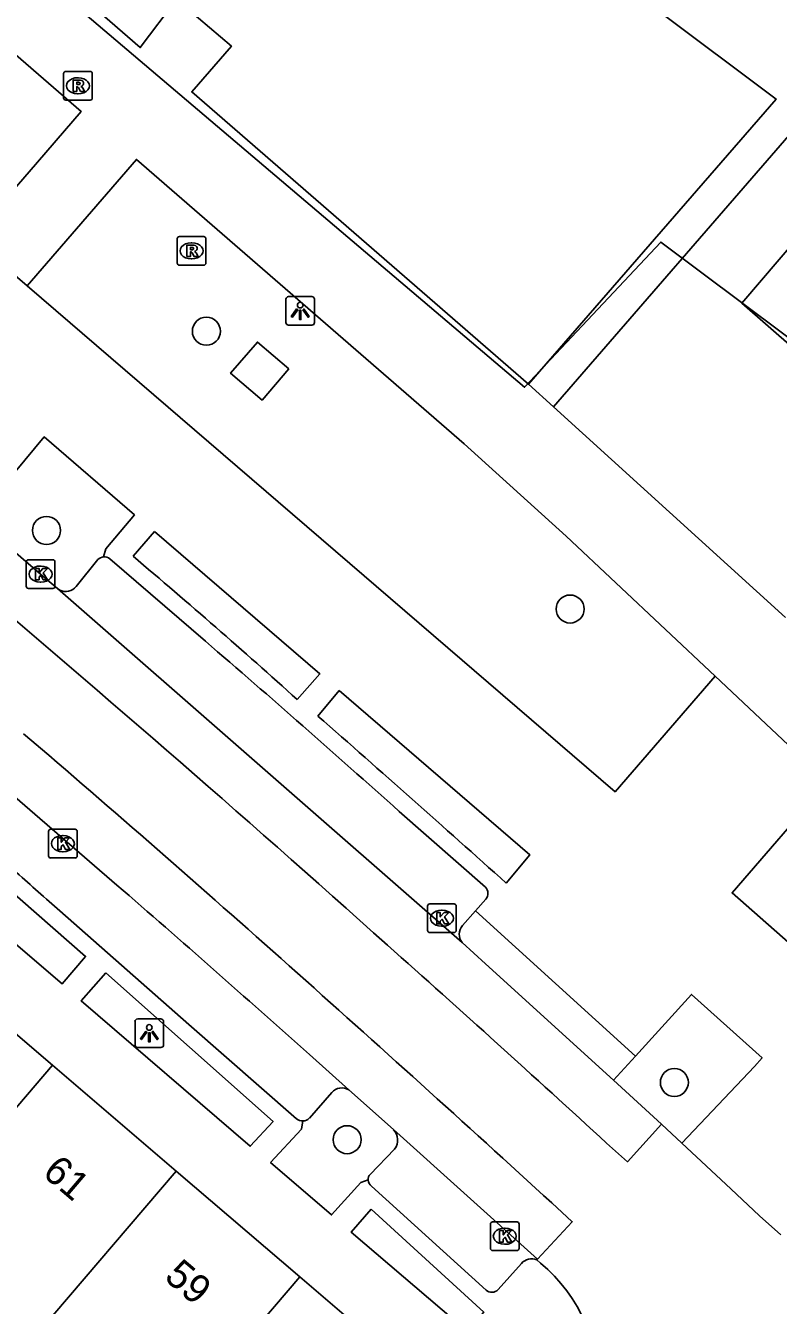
# Model space of a CAD drawing. Extents: x 159718 to 160783, y 383290 to 384030.
# Drawn here: x 160388.25 to 160414.5, y 383658.33 to 383702.97 of the extents above; entities that cross this region are included whole.
import ezdxf

# ---------------------------------------------------------------- set-up
doc = ezdxf.new("R2010")
doc.units = 0
for name, color, linetype in [('IMGEO_Boom', 7, 'Continuous'), ('IMGEO_Groenvoorziening', 7, 'Continuous'), ('IMGEO_Kolk', 7, 'Continuous'), ('IMGEO_Lichtpunt', 7, 'Continuous'), ('IMGEO_Pand', 7, 'Continuous'), ('IMGEO_Pand_nummerreeks', 7, 'Continuous'), ('IMGEO_Pand_overbouw', 7, 'Continuous'), ('IMGEO_Parkeervlak_open', 7, 'Continuous'), ('IMGEO_Rijbaan_lokaal_gesloten', 7, 'Continuous'), ('IMGEO_Rijbaan_lokaal_open', 7, 'Continuous'), ('IMGEO_Rioolput', 7, 'Continuous'), ('IMGEO_Voetpad_open', 7, 'Continuous')]:
    doc.layers.add(name, color=color, linetype=linetype)

msp = doc.modelspace()

# ---------------------------------------------------------------- linework, layer by layer
at = {"layer": 'IMGEO_Boom'}
for centre in [(160394.554, 383692.31), (160388.977, 383685.362), (160407.24, 383682.62), (160410.875, 383666.105), (160399.463, 383664.11)]:
    msp.add_circle(centre, 0.489, dxfattribs=at)
at = {"layer": 'IMGEO_Groenvoorziening'}
msp.add_lwpolyline([(160397.427, 383690.994), (160396.331, 383691.934), (160395.399, 383690.847), (160396.495, 383689.907), (160397.427, 383690.994)], dxfattribs=at)
at = {"layer": 'IMGEO_Kolk'}
for p, q in [((160388.272, 383683.413), (160388.272, 383684.265)), ((160388.347, 383684.339), (160389.199, 383684.339)), ((160389.273, 383684.265), (160389.273, 383683.413)), ((160388.76, 383684.119), (160388.785, 383684.119)), ((160389.199, 383683.339), (160388.347, 383683.339)), ((160388.783, 383683.559), (160388.758, 383683.559)), ((160389.046, 383674.01), (160389.046, 383674.862)), ((160389.121, 383674.936), (160389.973, 383674.936)), ((160390.047, 383674.862), (160390.047, 383674.01)), ((160389.534, 383674.716), (160389.559, 383674.716)), ((160389.973, 383673.936), (160389.121, 383673.936)), ((160389.557, 383674.156), (160389.532, 383674.156)), ((160402.268, 383671.408), (160402.268, 383672.26)), ((160402.343, 383672.334), (160403.195, 383672.334)), ((160402.756, 383672.114), (160402.781, 383672.114)), ((160403.269, 383672.26), (160403.269, 383671.408)), ((160403.195, 383671.334), (160402.343, 383671.334)), ((160402.779, 383671.554), (160402.754, 383671.554)), ((160404.461, 383660.315), (160404.461, 383661.167)), ((160404.536, 383661.241), (160405.388, 383661.241)), ((160404.949, 383661.021), (160404.974, 383661.021)), ((160405.462, 383661.167), (160405.462, 383660.315)), ((160405.388, 383660.241), (160404.536, 383660.241)), ((160404.972, 383660.461), (160404.947, 383660.461))]:
    msp.add_line(p, q, dxfattribs=at)
for points in [[(160388.272, 383683.413), (160388.272, 383684.265)], [(160388.347, 383684.339), (160389.199, 383684.339)], [(160389.273, 383684.265), (160389.273, 383683.413)], [(160388.593, 383684.039), (160388.716, 383684.039), (160388.716, 383683.888), (160388.846, 383684.039), (160389.01, 383684.039), (160388.864, 383683.888), (160389.017, 383683.639), (160388.865, 383683.639), (160388.78, 383683.803), (160388.716, 383683.736), (160388.716, 383683.639), (160388.593, 383683.639), (160388.593, 383684.039)], [(160389.199, 383683.339), (160388.347, 383683.339)], [(160389.046, 383674.01), (160389.046, 383674.862)], [(160389.121, 383674.936), (160389.973, 383674.936)], [(160390.047, 383674.862), (160390.047, 383674.01)], [(160389.367, 383674.636), (160389.49, 383674.636), (160389.49, 383674.485), (160389.62, 383674.636), (160389.784, 383674.636), (160389.638, 383674.485), (160389.791, 383674.236), (160389.639, 383674.236), (160389.554, 383674.4), (160389.49, 383674.333), (160389.49, 383674.236), (160389.367, 383674.236), (160389.367, 383674.636)], [(160389.973, 383673.936), (160389.121, 383673.936)], [(160402.268, 383671.408), (160402.268, 383672.26)], [(160402.343, 383672.334), (160403.195, 383672.334)], [(160403.269, 383672.26), (160403.269, 383671.408)], [(160402.589, 383672.034), (160402.712, 383672.034), (160402.712, 383671.883), (160402.842, 383672.034), (160403.006, 383672.034), (160402.86, 383671.883), (160403.013, 383671.634), (160402.861, 383671.634), (160402.776, 383671.798), (160402.712, 383671.731), (160402.712, 383671.634), (160402.589, 383671.634), (160402.589, 383672.034)], [(160403.195, 383671.334), (160402.343, 383671.334)], [(160404.461, 383660.315), (160404.461, 383661.167)], [(160404.536, 383661.241), (160405.388, 383661.241)], [(160405.462, 383661.167), (160405.462, 383660.315)], [(160404.782, 383660.941), (160404.905, 383660.941), (160404.905, 383660.79), (160405.035, 383660.941), (160405.199, 383660.941), (160405.053, 383660.79), (160405.206, 383660.541), (160405.054, 383660.541), (160404.969, 383660.705), (160404.905, 383660.638), (160404.905, 383660.541), (160404.782, 383660.541), (160404.782, 383660.941)], [(160405.388, 383660.241), (160404.536, 383660.241)]]:
    msp.add_lwpolyline(points, dxfattribs=at)
for centre, start, end in [((160388.349, 383684.263), 91.552, 178.448), ((160388.349, 383684.263), 91.552, 178.448), ((160389.197, 383684.263), 1.552, 88.448), ((160389.197, 383684.263), 1.552, 88.448), ((160388.349, 383683.415), 181.552, 268.448), ((160388.349, 383683.415), 181.552, 268.448), ((160389.197, 383683.415), 271.552, 358.448), ((160389.197, 383683.415), 271.552, 358.448), ((160389.123, 383674.86), 91.552, 178.448), ((160389.123, 383674.86), 91.552, 178.448), ((160389.971, 383674.86), 1.552, 88.448), ((160389.971, 383674.86), 1.552, 88.448), ((160389.123, 383674.012), 181.552, 268.448), ((160389.123, 383674.012), 181.552, 268.448), ((160389.971, 383674.012), 271.552, 358.448), ((160389.971, 383674.012), 271.552, 358.448), ((160402.345, 383672.258), 91.552, 178.448), ((160402.345, 383672.258), 91.552, 178.448), ((160403.193, 383672.258), 1.552, 88.448), ((160403.193, 383672.258), 1.552, 88.448), ((160402.345, 383671.41), 181.552, 268.448), ((160402.345, 383671.41), 181.552, 268.448), ((160403.193, 383671.41), 271.552, 358.448), ((160403.193, 383671.41), 271.552, 358.448), ((160404.538, 383661.165), 91.552, 178.448), ((160404.538, 383661.165), 91.552, 178.448), ((160405.386, 383661.165), 1.552, 88.448), ((160405.386, 383661.165), 1.552, 88.448), ((160404.538, 383660.317), 181.552, 268.448), ((160404.538, 383660.317), 181.552, 268.448), ((160405.386, 383660.317), 271.552, 358.448), ((160405.386, 383660.317), 271.552, 358.448)]:
    msp.add_arc(centre, 0.0765, start, end, dxfattribs=at)
for centre, major_axis, ratio, start_param, end_param in [((160388.759, 383683.839), (-0.387, 0.002), 0.722429, 4.712389, 7.853982), ((160388.784, 383683.839), (-0.39, 0.002), 0.717154, 1.570796, 4.712389), ((160389.533, 383674.436), (-0.387, 0.002), 0.722429, 4.712389, 7.853982), ((160389.558, 383674.436), (-0.39, 0.002), 0.717154, 1.570796, 4.712389), ((160402.755, 383671.834), (-0.387, 0.002), 0.722429, 4.712389, 7.853982), ((160402.78, 383671.834), (-0.39, 0.002), 0.717154, 1.570796, 4.712389), ((160404.948, 383660.741), (-0.387, 0.002), 0.722429, 4.712389, 7.853982), ((160404.973, 383660.741), (-0.39, 0.002), 0.717154, 1.570796, 4.712389)]:
    msp.add_ellipse(centre, major_axis=major_axis, ratio=ratio, start_param=start_param, end_param=end_param, dxfattribs=at)
at = {"layer": 'IMGEO_Lichtpunt'}
for p, q in [((160397.328, 383693.423), (160397.328, 383692.616)), ((160397.328, 383693.423), (160397.328, 383692.616)), ((160398.23, 383693.518), (160397.422, 383693.518)), ((160398.23, 383693.518), (160397.422, 383693.518)), ((160398.324, 383692.616), (160398.324, 383693.423)), ((160398.324, 383692.616), (160398.324, 383693.423)), ((160397.422, 383692.522), (160398.23, 383692.522)), ((160397.422, 383692.522), (160398.23, 383692.522)), ((160392.064, 383668.227), (160392.064, 383667.42)), ((160392.064, 383668.227), (160392.064, 383667.42)), ((160392.966, 383668.322), (160392.158, 383668.322)), ((160392.966, 383668.322), (160392.158, 383668.322)), ((160393.06, 383667.42), (160393.06, 383668.227)), ((160393.06, 383667.42), (160393.06, 383668.227)), ((160392.158, 383667.326), (160392.966, 383667.326)), ((160392.158, 383667.326), (160392.966, 383667.326))]:
    msp.add_line(p, q, dxfattribs=at)
for points in [[(160397.702, 383693.087), (160397.741, 383693.059), (160397.553, 383692.797), (160397.515, 383692.824), (160397.702, 383693.087)], [(160397.804, 383693.039), (160397.851, 383693.039), (160397.851, 383692.717), (160397.804, 383692.717), (160397.804, 383693.039)], [(160397.914, 383693.059), (160397.952, 383693.086), (160398.139, 383692.824), (160398.1, 383692.796), (160397.914, 383693.059)], [(160392.438, 383667.891), (160392.477, 383667.863), (160392.289, 383667.601), (160392.251, 383667.628), (160392.438, 383667.891)], [(160392.54, 383667.843), (160392.587, 383667.843), (160392.587, 383667.521), (160392.54, 383667.521), (160392.54, 383667.843)], [(160392.65, 383667.863), (160392.688, 383667.89), (160392.875, 383667.628), (160392.836, 383667.6), (160392.65, 383667.863)]]:
    msp.add_lwpolyline(points, dxfattribs=at)
for centre in [(160397.827, 383693.221), (160392.563, 383668.025)]:
    msp.add_circle(centre, 0.0994, dxfattribs=at)
for centre, start, end in [((160397.422, 383693.423), 90, 180), ((160397.422, 383693.423), 90, 180), ((160398.23, 383693.423), 0, 90), ((160398.23, 383693.423), 0, 90), ((160397.422, 383692.616), 180, 270), ((160397.422, 383692.616), 180, 270), ((160398.23, 383692.616), 270, 0), ((160398.23, 383692.616), 270, 360), ((160392.158, 383668.227), 90, 180), ((160392.158, 383668.227), 90, 180), ((160392.966, 383668.227), 0, 90), ((160392.966, 383668.227), 0, 90), ((160392.158, 383667.42), 180, 270), ((160392.158, 383667.42), 180, 270), ((160392.966, 383667.42), 270, 0), ((160392.966, 383667.42), 270, 360)]:
    msp.add_arc(centre, 0.0946, start, end, dxfattribs=at)
at = {"layer": 'IMGEO_Pand'}
for points in [[(160401.99, 383715.21), (160399.21, 383711.499), (160401.631, 383709.396), (160401.952, 383709.766), (160414.42, 383700.405), (160405.79, 383690.466)], [(160405.79, 383690.466), (160394.044, 383700.656), (160395.427, 383702.249), (160393.513, 383703.895), (160392.245, 383702.203), (160378.05, 383714.53)], [(160384.875, 383670.399), (160389.186, 383666.706)], [(160389.186, 383666.706), (160380.109, 383656.074), (160379.984, 383655.928)], [(160393.496, 383663.015), (160389.186, 383666.706)], [(160393.496, 383663.015), (160388.65, 383657.338)], [(160397.807, 383659.322), (160393.496, 383663.015)], [(160397.807, 383659.322), (160388.712, 383648.669)], [(160402.121, 383655.627), (160397.807, 383659.322)]]:
    msp.add_lwpolyline(points, dxfattribs=at)
at = {"layer": 'IMGEO_Pand_overbouw'}
msp.add_lwpolyline([(160329.238, 383785.121), (160331.99, 383780.945), (160334.29, 383776.804), (160336.214, 383773.114), (160339.132, 383767.518), (160356.871, 383731.789), (160405.652, 383690.358), (160410.402, 383695.422), (160427.513, 383682.61), (160420.977, 383676.643), (160427.906, 383670.57), (160434.977, 383677.001), (160452.682, 383663.643), (160457.733, 383668.166), (160454.133, 383672.121), (160456.593, 383674.32), (160452.291, 383679.222), (160501.162, 383722.964), (160422.396, 383781.748), (160424.644, 383785.027)], dxfattribs=at)
at = {"layer": 'IMGEO_Parkeervlak_open'}
for points in [[(160390.009, 383683.409), (160390.773, 383684.349)], [(160389.361, 383683.332), (160389.44, 383683.28)], [(160398.144, 383664.855), (160398.931, 383665.755)], [(160400.264, 383662.9), (160401.116, 383663.785)]]:
    msp.add_lwpolyline(points, dxfattribs=at)
for centre, radius, start, end in [((160390.993, 383684.119), 0.318, 94.8322, 133.6974), ((160389.648, 383683.684), 0.454, 242.8196, 322.728), ((160399.279, 383665.463), 0.454, 58.1088, 140.0566), ((160397.913, 383665.102), 0.338, 271.5028, 313.0756), ((160400.707, 383664.103), 0.518, 322.1077, 43.4901), ((160400.472, 383662.714), 0.279, 138.211, 181.3943)]:
    msp.add_arc(centre, radius, start, end, dxfattribs=at)
at = {"layer": 'IMGEO_Rijbaan_lokaal_gesloten'}
for points in [[(160389.361, 383683.332), (160388.773, 383683.839), (160386.776, 383685.54)], [(160403.476, 383670.988), (160389.361, 383683.332)], [(160385.346, 383678.241), (160391.435, 383672.99)], [(160403.476, 383670.988), (160404.289, 383670.243), (160408.752, 383666.186)], [(160398.15, 383667.079), (160399.519, 383665.849)], [(160408.752, 383666.186), (160410.425, 383664.652)], [(160399.519, 383665.849), (160401.083, 383664.46)], [(160410.425, 383664.652), (160409.243, 383663.343), (160408.512, 383663.988)], [(160401.083, 383664.46), (160406.096, 383659.939)], [(160406.597, 383661.904), (160407.312, 383661.248), (160406.096, 383659.939)]]:
    msp.add_lwpolyline(points, dxfattribs=at)
for centre, radius, start, end in [((159981.002, 383203.227), 628.491, 48.083345, 49.955777), ((160019.112, 383246.774), 567.802, 48.21724, 49.45909), ((159962.952, 383179.456), 653.586, 48.251445, 49.035692), ((159988.807, 383207.205), 620.325, 47.422346, 48.374311), ((159862.316, 383068.426), 805.269, 47.47592, 48.353539)]:
    msp.add_arc(centre, radius, start, end, dxfattribs=at)
at = {"layer": 'IMGEO_Rijbaan_lokaal_open'}
for points in [[(160411.138, 383663.99), (160410.425, 383664.652)], [(160411.138, 383663.99), (160412.842, 383662.391), (160413.843, 383661.455), (160414.587, 383660.793)], [(160406.096, 383659.939), (160406.076, 383659.917)], [(160406.212, 383659.805), (160406.076, 383659.917)]]:
    msp.add_lwpolyline(points, dxfattribs=at)
msp.add_arc((160402.51, 383655.424), 5.736, 356.9945, 49.8038, dxfattribs=at)
at = {"layer": 'IMGEO_Rioolput'}
for p, q in [((160389.574, 383700.447), (160389.574, 383701.299)), ((160389.649, 383701.373), (160390.501, 383701.373)), ((160390.062, 383701.153), (160390.087, 383701.153)), ((160390.575, 383701.299), (160390.575, 383700.447)), ((160390.501, 383700.373), (160389.649, 383700.373)), ((160390.085, 383700.593), (160390.06, 383700.593)), ((160393.536, 383694.687), (160393.536, 383695.539)), ((160393.611, 383695.613), (160394.463, 383695.613)), ((160394.024, 383695.393), (160394.049, 383695.393)), ((160394.537, 383695.539), (160394.537, 383694.687)), ((160394.463, 383694.613), (160393.611, 383694.613)), ((160394.047, 383694.833), (160394.022, 383694.833))]:
    msp.add_line(p, q, dxfattribs=at)
for points in [[(160389.574, 383700.447), (160389.574, 383701.299)], [(160389.649, 383701.373), (160390.501, 383701.373)], [(160390.575, 383701.299), (160390.575, 383700.447)], [(160390.163, 383701.071), (160389.911, 383701.073), (160389.911, 383700.673)], [(160389.911, 383700.673), (160390.035, 383700.673), (160390.035, 383700.835), (160390.046, 383700.835)], [(160390.089, 383700.992), (160390.035, 383700.992), (160390.035, 383700.911)], [(160390.035, 383700.911), (160390.087, 383700.911)], [(160390.093, 383700.806), (160390.164, 383700.673), (160390.304, 383700.673), (160390.239, 383700.799)], [(160390.501, 383700.373), (160389.649, 383700.373)], [(160393.536, 383694.687), (160393.536, 383695.539)], [(160393.611, 383695.613), (160394.463, 383695.613)], [(160394.537, 383695.539), (160394.537, 383694.687)], [(160394.125, 383695.311), (160393.873, 383695.313), (160393.873, 383694.913)], [(160393.873, 383694.913), (160393.997, 383694.913), (160393.997, 383695.075), (160394.008, 383695.075)], [(160394.051, 383695.232), (160393.997, 383695.232), (160393.997, 383695.151)], [(160393.997, 383695.151), (160394.049, 383695.151)], [(160394.055, 383695.046), (160394.126, 383694.913), (160394.266, 383694.913), (160394.201, 383695.039)], [(160394.463, 383694.613), (160393.611, 383694.613)]]:
    msp.add_lwpolyline(points, dxfattribs=at)
for centre, radius, start, end in [((160389.651, 383701.297), 0.0765, 91.552, 178.448), ((160389.651, 383701.297), 0.0765, 91.552, 178.448), ((160390.499, 383701.297), 0.0765, 1.552, 88.448), ((160390.499, 383701.297), 0.0765, 1.552, 88.448), ((160390.045, 383700.782), 0.0533, 26.0293, 88.6989), ((160390.071, 383701.1), 0.19, 274.7715, 282.9687), ((160390.095, 383700.896), 0.0964, 77.0061, 93.1865), ((160390.109, 383700.953), 0.0378, 276.6634, 79.6772), ((160390.162, 383700.961), 0.109, 350.3612, 89.416), ((160390.16, 383700.961), 0.112, 277.5842, 350.9817), ((160390.144, 383700.746), 0.108, 29.5134, 73.7905), ((160389.651, 383700.449), 0.0765, 181.552, 268.448), ((160389.651, 383700.449), 0.0765, 181.552, 268.448), ((160390.499, 383700.449), 0.0765, 271.552, 358.448), ((160390.499, 383700.449), 0.0765, 271.552, 358.448), ((160393.613, 383695.537), 0.0765, 91.552, 178.448), ((160393.613, 383695.537), 0.0765, 91.552, 178.448), ((160394.461, 383695.537), 0.0765, 1.552, 88.448), ((160394.461, 383695.537), 0.0765, 1.552, 88.448), ((160394.007, 383695.022), 0.0533, 26.0293, 88.6989), ((160394.033, 383695.34), 0.19, 274.7715, 282.9687), ((160394.057, 383695.136), 0.0964, 77.0061, 93.1865), ((160394.071, 383695.193), 0.0378, 276.6634, 79.6772), ((160394.124, 383695.201), 0.109, 350.3612, 89.416), ((160394.122, 383695.201), 0.112, 277.5842, 350.9817), ((160394.106, 383694.986), 0.108, 29.5134, 73.7905), ((160393.613, 383694.689), 0.0765, 181.552, 268.448), ((160393.613, 383694.689), 0.0765, 181.552, 268.448), ((160394.461, 383694.689), 0.0765, 271.552, 358.448), ((160394.461, 383694.689), 0.0765, 271.552, 358.448)]:
    msp.add_arc(centre, radius, start, end, dxfattribs=at)
for centre, major_axis, ratio, start_param, end_param in [((160390.061, 383700.873), (-0.387, 0.002), 0.722429, 4.712389, 7.853982), ((160390.086, 383700.873), (-0.39, 0.002), 0.717154, 1.570796, 4.712389), ((160394.023, 383695.113), (-0.387, 0.002), 0.722429, 4.712389, 7.853982), ((160394.048, 383695.113), (-0.39, 0.002), 0.717154, 1.570796, 4.712389)]:
    msp.add_ellipse(centre, major_axis=major_axis, ratio=ratio, start_param=start_param, end_param=end_param, dxfattribs=at)
at = {"layer": 'IMGEO_Voetpad_open'}
for points in [[(160373.434, 383714.511), (160390.192, 383699.969), (160388.371, 383697.872), (160386.357, 383695.552)], [(160406.662, 383689.674), (160415.253, 383699.577), (160417.14, 383697.859)], [(160388.301, 383693.898), (160392.112, 383698.303), (160403.549, 383688.378), (160407.103, 383685.162), (160412.294, 383680.279)], [(160417.14, 383697.859), (160413.231, 383693.288), (160419.662, 383687.67)], [(160388.301, 383693.898), (160386.357, 383695.552)], [(160412.294, 383680.279), (160408.805, 383676.246), (160388.301, 383693.898)], [(160406.662, 383689.674), (160405.79, 383690.466)], [(160414.756, 383682.321), (160406.662, 383689.674)], [(160387.607, 383687.297), (160387.881, 383687.406), (160388.897, 383688.625), (160392.042, 383685.9), (160391.049, 383684.717), (160390.966, 383684.436)], [(160391.995, 383684.461), (160392.739, 383685.319)], [(160392.739, 383685.319), (160398.512, 383680.358), (160397.724, 383679.46)], [(160391.188, 383684.375), (160394.521, 383681.496)], [(160416.224, 383676.581), (160412.294, 383680.279)], [(160398.444, 383678.888), (160399.18, 383679.774)], [(160399.18, 383679.774), (160405.835, 383674.044), (160405.011, 383673.06)], [(160421.375, 383664.839), (160418.849, 383667.474), (160412.886, 383672.715), (160416.224, 383676.581)], [(160384.626, 383675.494), (160390.343, 383670.505), (160389.525, 383669.55), (160383.759, 383674.476), (160384.626, 383675.494)], [(160401.272, 383675.563), (160404.284, 383672.919)], [(160404.297, 383672.502), (160403.94, 383672.094)], [(160397.699, 383664.837), (160393.945, 383668.124), (160389.447, 383672.088)], [(160403.94, 383672.094), (160403.487, 383671.576)], [(160403.94, 383672.094), (160409.515, 383667.025)], [(160391.042, 383669.935), (160396.877, 383664.744), (160396.081, 383663.884), (160390.187, 383668.948), (160391.042, 383669.935)], [(160409.515, 383667.025), (160411.471, 383669.176), (160413.936, 383666.961), (160413.67, 383666.666), (160411.138, 383663.99)], [(160409.515, 383667.025), (160408.752, 383666.186)], [(160400.193, 383662.707), (160399.944, 383662.621), (160398.92, 383661.487), (160396.793, 383663.317), (160397.868, 383664.475), (160397.922, 383664.764)], [(160404.307, 383658.862), (160400.309, 383662.487)], [(160400.295, 383661.684), (160404.227, 383658.097), (160403.647, 383657.427), (160399.608, 383660.884), (160400.295, 383661.684)], [(160405.543, 383659.79), (160404.725, 383658.882)]]:
    msp.add_lwpolyline(points, dxfattribs=at)
for centre, radius, start, end in [((160390.998, 383684.117), 0.321, 53.6144, 95.6571), ((160248.762, 383514.595), 222.194, 47.90087, 49.86195), ((160113.901, 383355.378), 430.233, 48.09147, 49.2884), ((159890.516, 383099.94), 770.176, 48.085389, 48.738575), ((160452.94, 383745.2), 96.833, 227.83211, 229.02795), ((160404.065, 383672.703), 0.307, 319.0363, 44.5349), ((160403.817, 383671.276), 0.446, 137.7135, 220.1431), ((160397.911, 383665.109), 0.345, 231.9995, 271.7483), ((160400.47, 383662.712), 0.277, 181.0858, 234.5171), ((160405.892, 383659.509), 0.448, 65.6724, 141.1319), ((160404.506, 383659.091), 0.303, 229.111, 316.3676)]:
    msp.add_arc(centre, radius, start, end, dxfattribs=at)

# ---------------------------------------------------------------- texts
at = {"layer": 'IMGEO_Pand_nummerreeks'}
for s, p in [('61', (160388.792, 383662.889)), ('59', (160393.043, 383659.26))]:
    msp.add_text(s, height=1, rotation=319.5148, dxfattribs=at).set_placement(p)

doc.saveas('drawing.dxf')
